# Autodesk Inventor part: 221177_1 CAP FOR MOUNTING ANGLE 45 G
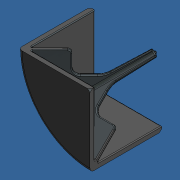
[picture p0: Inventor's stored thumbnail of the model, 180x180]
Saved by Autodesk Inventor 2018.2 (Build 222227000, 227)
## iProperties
Created: 2019-06
Part Number: 221177_1 CAP FOR MOUNTING ANGLE 45 G
Material: PA 6 GF 30
Description: Abdeckkappe MW 45/45/45 grau
Document SubType Name: Modeling
Designer: amoles
Density: 1.06 g/cm^3
Appearance: Gray
Sending System: Autodesk Inventor 2019
Preprocessor: ST-DEVELOPER v17.2
Title: C:\Users\muellerj\Daten Sicherung von Allen\STEP-Daten Artikel\221177-1.stp
Author: muellerj
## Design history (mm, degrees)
feature "Volumenkörper1"
body "Solid1"
